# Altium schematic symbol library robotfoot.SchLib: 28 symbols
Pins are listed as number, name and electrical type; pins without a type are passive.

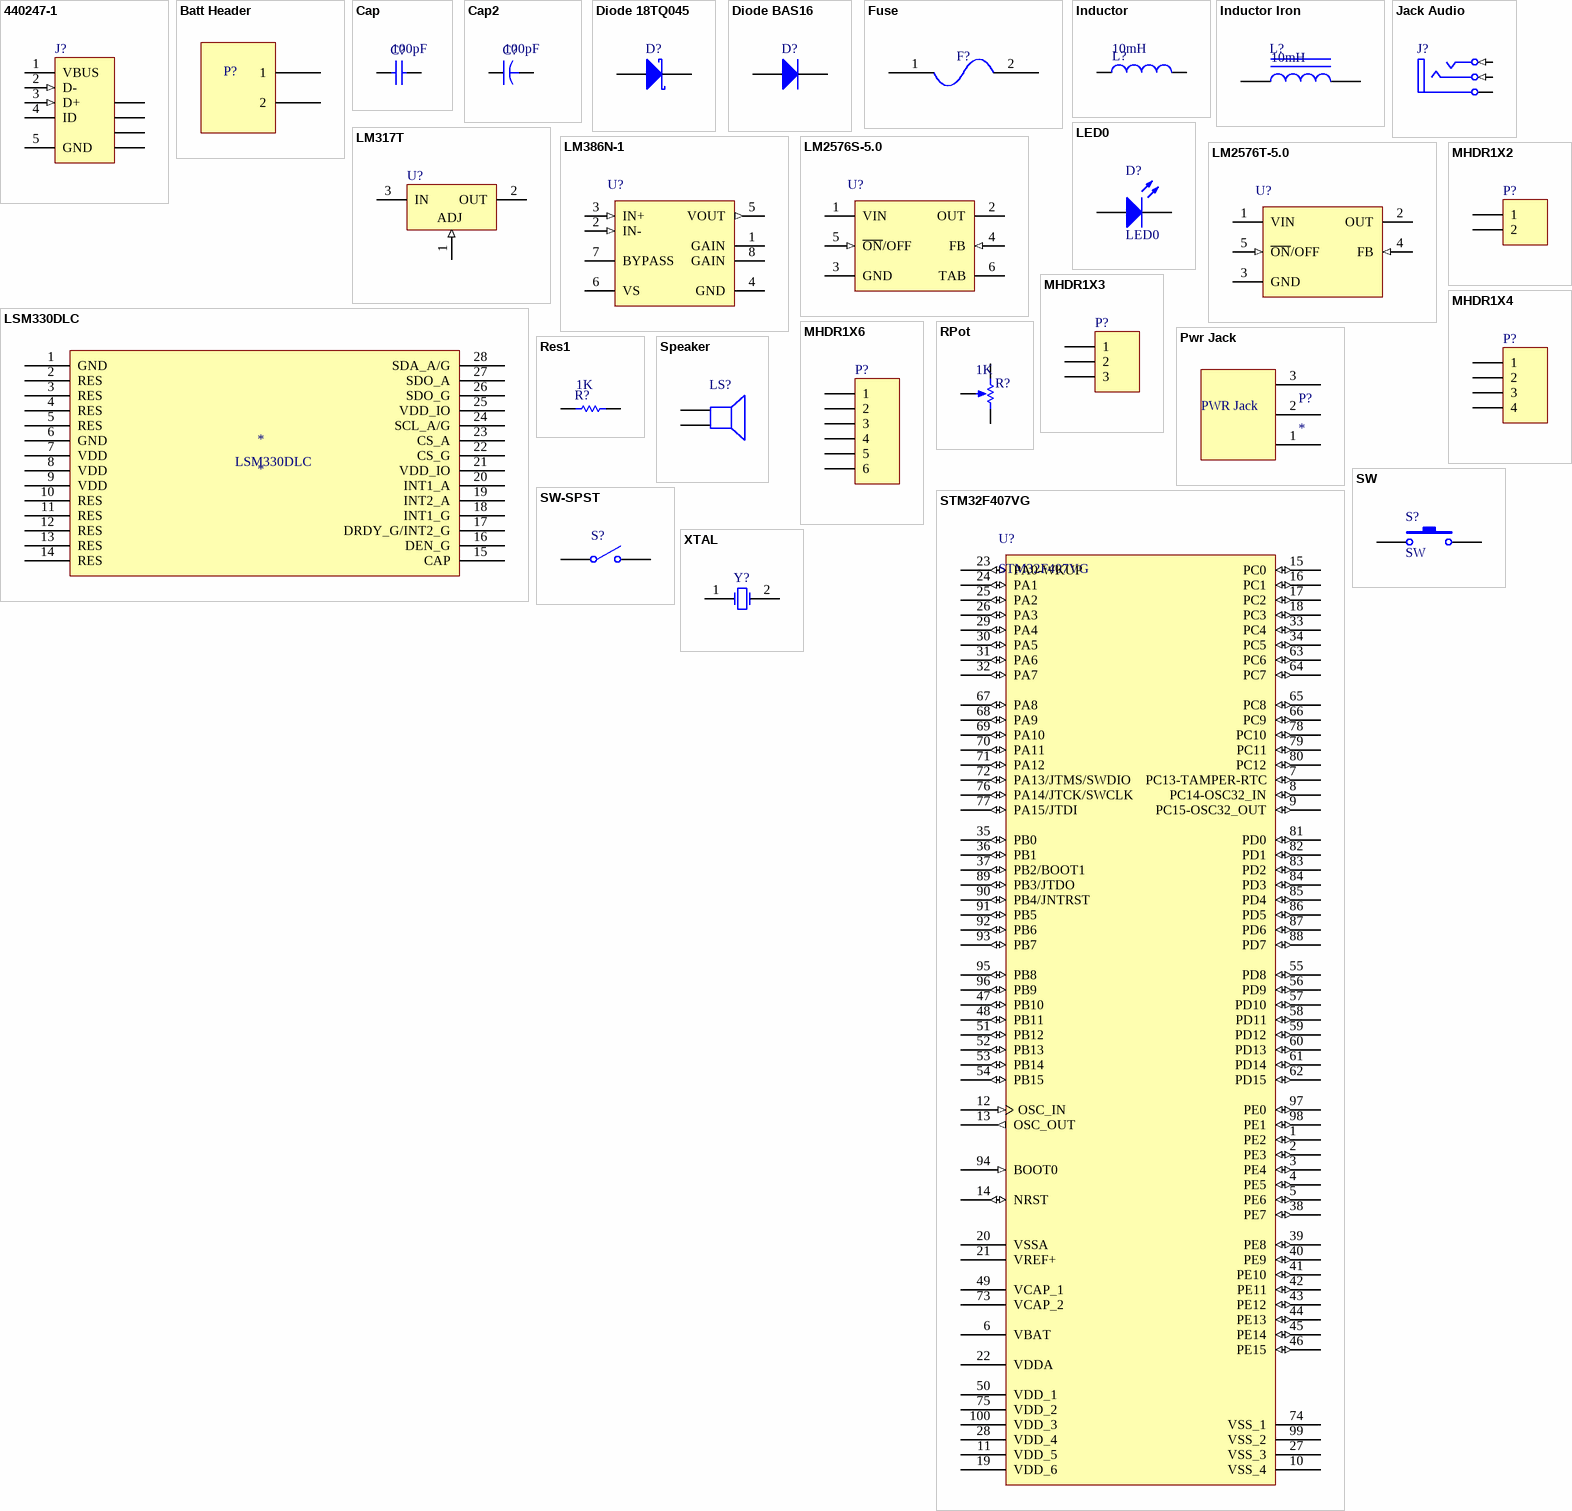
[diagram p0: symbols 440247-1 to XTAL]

## 440247-1
designator J?
USB 2.0, Right Angle, SMT, B Type, Receptacle, 5 Position, Black; ContactMaterial: Copper Alloy; ContactPlating: Gold (30); PCB_Layout: Complies with manufacturer's recommendation.; DrillSize: Corresponds to nominal value.; PanelGround: Without
signal-integrity model USB2.0
footprint 440247 (Connector; USB2.0, Type B, SM; 5 Position; Right Angle)
pins: 1 VBUS (power) "Power", 2 D- (in) "-DATA", 3 D+ (in) "+DATA", 4 ID (power) "Ground", 5 GND "Shield", 6 SHLD "Shield", 7 SHLD "Shield", 8 SHLD "Shield", 9 SHLD "Shield"

## Batt Header
designator P?  (value not drawn)
footprint BATTFOOT
pins: 1, 2

## Cap
designator C?  value 100pF  (hidden comment: Cap)
Capacitor
footprint RAD-0.3 (Radial Cap, Thru-Hole; 2 Leads; 0.3 in Pin Spacing)
simulation model CAP (Capacitor)
signal-integrity model Cap
footprint 0402 (Chip Capacitor, Body 1.0x0.5mm, IPC High Density)
footprint 1608[0603] (Chip Capacitor, Body 1.6x0.8mm, IPC High Density)
footprint C1206 (Chip Capacitor, Body 3.2x1.6mm, IPC High Density)
footprint C1210 (Chip Capacitor, Body 3.2x2.5mm, IPC High Density)
footprint C2512 (Chip Capacitor, Body 2.54x1.27mm, IPC High Density)
footprint C0805 (Chip Capacitor, Body 2.0x1.3mm, IPC High Density)
pins: 1, 2

## Cap2
designator C?  value 100pF  (hidden comment: Cap2)
Capacitor
simulation model CAP (Capacitor)
signal-integrity model Cap
footprint CAPR5-4X5 (Capacitor; 2 Leads)
footprint 1812 (Chip Capacitor, Body 4.5x3.2mm, IPC High Density)
footprint 1825 (Chip Capacitor, Body 4.5x6.4mm, IPC High Density)
footprint 2220 (Chip Capacitor, Body 5.7x5.0mm, IPC High Density)
footprint C0805 (Chip Capacitor, Body 2.0x1.3mm, IPC High Density)
footprint C2225 (Chip Capacitor, Body 5.7x6.4mm, IPC High Density)
footprint C1206 (Chip Capacitor, Body 3.2x1.6mm, IPC High Density)
footprint RB7.6-15 (Polarized Capacitor (Radial); 2 Leads)
footprint EEE-1EA101XP
footprint urs1v102 (Polarized Capacitor (Radial); 2 Leads)
pins: 1, 2

## Diode 18TQ045
designator D?
Schottky Rectifier; Note: Terminal 2 is the TAB and is electrically connected to the cathode
simulation model 18TQ045 (DIODE)
footprint TO-220AC (TO, Thru-Hole, Vertical, Heatsink Mounted; 3 In-Line Leads (1 Absent); Pitch 2.54 mm)
footprint DO-220AA
pins: 1 K, 2 A

## Diode BAS16
designator D?
Silicon Switching Diode for High-Speed Switching; Note: Pin 2 is not connected and not drawn.
simulation model BAS16 (SUBCKT)
footprint SOT-23_L (SOT23, 3-Leads, Body 2.9x1.3mm, Pitch 0.95mm, Lead Span 2.5mm, IPC High Density)
footprint SOT-23_M (SOT23, 3-Leads, Body 2.9x1.3mm, Pitch 0.95mm, Lead Span 2.5mm, IPC Low Density)
footprint SOT-23_N (SOT23, 3-Leads, Body 2.9x1.3mm, Pitch 0.95mm, Lead Span 2.5mm, IPC Medium Density)
pins: 1 A, 3 K

## Fuse
designator F?  (value not drawn)
footprint Fuseholder
pins: 1, 2

## Inductor
designator L?  value 10mH
Inductor; Code_IEC: 1005
simulation model INDUCTOR (Inductor)
signal-integrity model Inductor
footprint 0402-A (Chip Inductor, Body 1.0x0.5mm, IPC High Density)
footprint 0603 (Chip Inductor, Body 0.6x0.3mm, IPC High Density)
footprint 2029 (Chip Inductor, Body 2.0x1.2mm, IPC High Density)
footprint INDC1608L (Chip Inductor, Body 1.6x0.8mm, IPC High Density)
footprint INDC3216 (Chip Inductor, Body 3.2x1.6mm, IPC High Density)
footprint INDC4532 (Chip Inductor, Body 4.5x3.2mm, IPC High Density)
pins: 1, 2

## Inductor Iron
designator L?  value 10mH
Magnetic-Core Inductor
simulation model INDUCTOR (Inductor)
signal-integrity model Inductor Iron
footprint AXIAL-0.9 (Axial Device, Thru-Hole; 2 Leads; 0.9 in Pin Spacing)
footprint Coil
pins: 1, 2

## Jack Audio
designator J?
Stereo Jack 3.5mm; PCB_Layout: Complies with manufacturer's recommendation.
signal-integrity model Audio Jack
footprint Jack Audio (Connector; Stereo Jack 3.5mm)
pins: 1 S (power) "Sleeve (Ground)", 2 T (in) "Tip/Left Channel/(+)", 3 R (in) "Ring/Right Channel/(-)"

## LED0
designator D?
Typical INFRARED GaAs LED
simulation model LED0 (Diode)
footprint LED-0 (LED; 2 Leads)
footprint 3.2X1.6X1.1 (SMT LED; 2 Flat Leads)
footprint 3.5X2.8X1.9 (SM LED; 2 C-Bend Leads; Body 3.5 x 2.8 x 1.9 mm, inc leads (LxWxH typ))
pins: 1 A, 2 K

## LM317T
designator U?
3-Terminal Adjustable Regulator, 3-pin TO-220; PartNumber: LM317T; Manufacturer: National Semiconductor; PackageTopMarking: NSUZXYTTE#*LM317T P+; PowerWise: N; CompType: LDO IC
footprint T03B (TO, Thru-Hole, Vertical, Heatsink Mounted; 3 In-Line Leads; Pitch 2.54 mm)
pins: 1 ADJ (in), 2 OUT (power), 3 IN (power)

## LM386N-1
designator U?
Low Voltage Audio Power Amplifier, 8-pin MDIP; PartNumber: LM386N-1; Manufacturer: National Semiconductor; PackageTopMarking: NSUZXYTTE#*LM*386N-1; PowerWise: N; CompType: Audio IC
footprint N08E (DIP, 8-Leads, Row Spacing 7.62mm, Pitch 2.54mm, Body 9.91x6.35mm)
pins: 1 GAIN, 2 IN- (in), 3 IN+ (in), 4 GND (power), 5 VOUT (out), 6 VS (power), 7 BYPASS, 8 GAIN

## LM2576S-5.0
designator U?
SIMPLE SWITCHER® 3A Step-Down Voltage Regulator, 5-pin TO-263; PartNumber: LM2576S-5.0; Manufacturer: National Semiconductor; PackageTopMarking: NSUZXYTTE#*LM2576S*-5.0 P+; PowerWise: N
footprint TS5B_L (D2-PAK, 6-Leads, Body 8.6x10.2mm, Pitch 1.7mm, Lead Span 14.1mm, IPC High Density)
footprint TS5B_M (D2-PAK, 6-Leads, Body 8.6x10.2mm, Pitch 1.7mm, Lead Span 14.1mm, IPC Low Density)
footprint TS5B_N (D2-PAK, 6-Leads, Body 8.6x10.2mm, Pitch 1.7mm, Lead Span 14.1mm, IPC Medium Density)
pins: 1 VIN (power), 2 OUT (power), 3 GND (power), 4 FB (in), 5 ~{ON}/OFF (in), 6 TAB (power)

## LM2576T-5.0
designator U?
SIMPLE SWITCHER® 3A Step-Down Voltage Regulator, 5-pin TO-220; PartNumber: LM2576T-5.0; Manufacturer: National Semiconductor; PackageTopMarking: NSUZXYTTE#*LM2576T*-5.0 P+; PowerWise: N
footprint T05A (TO, Thru-Hole, Vertical, Heatsink Mounted; 5 In-Line Leads; Pitch 1.70 mm)
pins: 1 VIN (power), 2 OUT (power), 3 GND (power), 4 FB (in), 5 ~{ON}/OFF (in)

## LSM330DLC
designator *
3D Accelerometer/Gyroscope
footprint ACC/GYR
pins: 1 GND, 2 RES, 3 RES, 4 RES, 5 RES, 6 GND, 7 VDD, 8 VDD, 9 VDD, 10 RES, 11 RES, 12 RES, 13 RES, 14 RES, 15 CAP, 16 DEN_G, 17 DRDY_G/INT2_G, 18 INT1_G, 19 INT2_A, 20 INT1_A, 21 VDD_IO, 22 CS_G, 23 CS_A, 24 SCL_A/G, 25 VDD_IO, 26 SDO_G, 27 SDO_A, 28 SDA_A/G

## MHDR1X2
designator P?
Header, 2-Pin
signal-integrity model Connector
footprint MHDR1X2 (Connector; Header; 2 Position)
pins: 1, 2

## MHDR1X3
designator P?
Header, 3-Pin
signal-integrity model Connector
footprint MHDR1X3 (Connector; Header; 3 Position)
pins: 1, 2, 3

## MHDR1X4
designator P?
Header, 4-Pin
signal-integrity model Connector
footprint MHDR1X4 (Connector; Header; 4 Position)
pins: 1, 2, 3, 4

## MHDR1X6
designator P?
Header, 6-Pin
signal-integrity model Connector
footprint MHDR1X6 (Connector; Header; 6 Position)
pins: 1, 2, 3, 4, 5, 6

## Pwr Jack
designator P?
footprint PWR JACK
pins: 1, 2, 3

## Res1
designator R?  value 1K  (hidden comment: Res1)
Resistor
simulation model RESISTOR (Resistor)
signal-integrity model Res
footprint AXIAL-0.3 (Axial Device, Thru-Hole; 2 Leads; 0.3 in Pin Spacing)
footprint 12Z-2010 (Chip Resistor, Body 5.0x2.5mm, IPC High Density)
footprint 14-1210 (Chip Resistor, Body 3.2x2.5mm, IPC High Density)
footprint J1-0603 (Chip Resistor, Body 1.6x0.8mm, IPC High Density)
footprint RESC6332 (Chip Resistor, Body 6.3x3.2mm, IPC High Density)
pins: 1, 2

## RPot
designator R?  value 1K  (hidden comment: RPot)
Potentiometer; Sim Note: Enter the Resistance value and the set point into parameter fields.; Set Position: 0.5
simulation model POT (Potentiometer)
footprint VR5 (Thru-Hole; 3 Leads)
footprint Pot-3352 (Thru-Hole; 3 Leads)
pins: 1 TOP, 2 BOT, 3 TAP
1 alternate drawing of the same symbol

## Speaker
designator LS?
Loudspeaker
footprint PIN2 (Photosensitive Diode; 2 Leads)
pins: 1, 2

## STM32F407VG
designator U?
STM32 ARM-based 32-bit MCU with 64 Kbytes Flash, 100-pin LQFP, Industrial Temperature
footprint LQFP100_L (Thin QFP, 100-Leads, Body 14x14mm, Pitch 0.5mm, IPC High Density)
footprint LQFP100_M (Thin QFP, 100-Leads, Body 14x14mm, Pitch 0.5mm, IPC Low Density)
footprint LQFP100_N (Thin QFP, 100-Leads, Body 14x14mm, Pitch 0.5mm, IPC Medium Density)
pins: 1 PE2 (io), 2 PE3 (io), 3 PE4 (io), 4 PE5 (io), 5 PE6 (io), 6 VBAT (power), 7 PC13-TAMPER-RTC (io), 8 PC14-OSC32_IN (io), 9 PC15-OSC32_OUT (io), 10 VSS_4 (power), 11 VDD_5 (power), 12 OSC_IN (in), 13 OSC_OUT (out), 14 NRST (io), 15 PC0 (io), 16 PC1 (io), 17 PC2 (io), 18 PC3 (io), 19 VDD_6 (power), 20 VSSA (power), 21 VREF+ (power), 22 VDDA (power), 23 PA0-WKUP (io), 24 PA1 (io), 25 PA2 (io), 26 PA3 (io), 27 VSS_3 (power), 28 VDD_4 (power), 29 PA4 (io), 30 PA5 (io), 31 PA6 (io), 32 PA7 (io), 33 PC4 (io), 34 PC5 (io), 35 PB0 (io), 36 PB1 (io), 37 PB2/BOOT1 (io), 38 PE7 (io), 39 PE8 (io), 40 PE9 (io), 41 PE10 (io), 42 PE11 (io), 43 PE12 (io), 44 PE13 (io), 45 PE14 (io), 46 PE15 (io), 47 PB10 (io), 48 PB11 (io), 49 VCAP_1 (power), 50 VDD_1 (power), 51 PB12 (io), 52 PB13 (io), 53 PB14 (io), 54 PB15 (io), 55 PD8 (io), 56 PD9 (io), 57 PD10 (io), 58 PD11 (io), 59 PD12 (io), 60 PD13 (io), 61 PD14 (io), 62 PD15 (io), 63 PC6 (io), 64 PC7 (io), 65 PC8 (io), 66 PC9 (io), 67 PA8 (io), 68 PA9 (io), 69 PA10 (io), 70 PA11 (io), 71 PA12 (io), 72 PA13/JTMS/SWDIO (io), 73 VCAP_2, 74 VSS_1 (power), 75 VDD_2 (power), 76 PA14/JTCK/SWCLK (io), 77 PA15/JTDI (io), 78 PC10 (io), 79 PC11 (io), 80 PC12 (io), 81 PD0 (io), 82 PD1 (io), 83 PD2 (io), 84 PD3 (io), 85 PD4 (io), 86 PD5 (io), 87 PD6 (io), 88 PD7 (io), 89 PB3/JTDO (io), 90 PB4/JNTRST (io), 91 PB5 (io), 92 PB6 (io), 93 PB7 (io), 94 BOOT0 (in), 95 PB8 (io), 96 PB9 (io), 97 PE0 (io), 98 PE1 (io), 99 VSS_2 (power), 100 VDD_3 (power)

## SW
designator S?
Switch
footprint Switch (Switch; 2 Leads)
pins: 1, 2

## SW-SPST
designator S?
Single-Pole, Single-Throw Switch
footprint Switch on-off
pins: 1 COMMON, 2 NO

## XTAL
designator Y?
Crystal Oscillator
simulation model XTAL (Spice Subcircuit)
footprint Crystal (Crystal, Thru-Hole; 2 Leads)
pins: 1 OSC1, 2 OSC2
